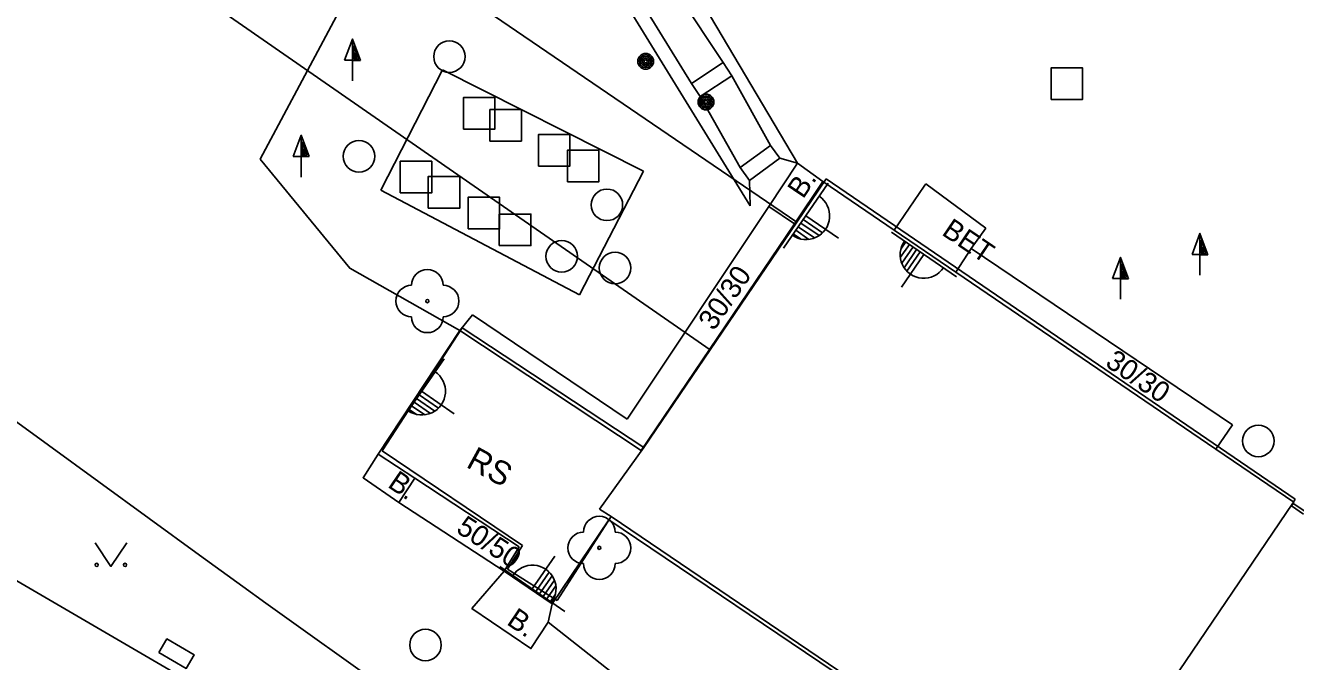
# Model space of a CAD drawing. Extents: x -540150 to -533593, y -1185082 to -1180066.
# Drawn here: x -536061.54 to -536021.28, y -1184550.12 to -1184529.96 of the extents above; entities that cross this region are included whole.
import ezdxf

# ---------------------------------------------------------------- set-up
doc = ezdxf.new("R2010")
doc.units = 0
for name, color, linetype in [('KN_HRAN_PARCEL', 7, 'Continuous'), ('KN_VKP_HRAN_', 7, 'Continuous'), ('Vrstva 10', 7, 'Continuous'), ('Vrstva 11', 7, 'Continuous'), ('Vrstva 22', 7, 'Continuous'), ('Vrstva 24', 7, 'Continuous'), ('Vrstva 25', 7, 'Continuous'), ('Vrstva 26', 7, 'Continuous'), ('Vrstva 27', 7, 'Continuous'), ('Vrstva 36', 7, 'Continuous'), ('Vrstva 37', 7, 'Continuous'), ('Vrstva 40', 7, 'Continuous'), ('Vrstva 41', 7, 'Continuous'), ('Vrstva 5', 7, 'Continuous'), ('Vrstva 7', 7, 'Continuous')]:
    doc.layers.add(name, color=color, linetype=linetype)

msp = doc.modelspace()

# ---------------------------------------------------------------- linework, layer by layer
at = {"layer": 'KN_HRAN_PARCEL'}
for p, q in [((-536036.161, -1184534.825), (-536037.091, -1184536.195)), ((-536021.291, -1184544.975), (-536036.161, -1184534.825)), ((-536037.091, -1184536.195), (-536039.841, -1184540.235)), ((-536047.701, -1184539.545), (-536050.231, -1184543.445)), ((-536041.941, -1184543.335), (-536047.701, -1184539.545)), ((-536039.841, -1184540.235), (-536041.941, -1184543.335)), ((-536050.231, -1184543.445), (-536045.781, -1184546.435)), ((-536021.371, -1184545.095), (-536021.291, -1184544.975)), ((-536019.161, -1184546.605), (-536021.371, -1184545.095)), ((-536044.691, -1184548.185), (-536042.971, -1184545.525)), ((-536042.971, -1184545.525), (-536028.361, -1184555.415)), ((-536045.781, -1184546.435), (-536046.261, -1184547.195)), ((-536046.261, -1184547.195), (-536044.691, -1184548.185))]:
    msp.add_line(p, q, dxfattribs=at)
at = {"layer": 'KN_VKP_HRAN_'}
for p, q in [((-536039.841, -1184540.235), (-536061.291, -1184525.355)), ((-536037.091, -1184536.195), (-536047.171, -1184529.325)), ((-536041.941, -1184543.335), (-536043.341, -1184545.285)), ((-536021.371, -1184545.095), (-536028.281, -1184555.295)), ((-536042.971, -1184545.525), (-536043.341, -1184545.285))]:
    msp.add_line(p, q, dxfattribs=at)
at = {"layer": 'Vrstva 10'}
for p, q in [((-536056.027, -1184546.748), (-536060.815, -1184543.257)), ((-536043.816, -1184555.48), (-536053.921, -1184548.265))]:
    msp.add_line(p, q, dxfattribs=at)
for points in [[(-536060.815, -1184543.257), (-536062.015, -1184542.388), (-536062.917, -1184541.739), (-536063.595, -1184541.254), (-536064.616, -1184540.532), (-536065.128, -1184540.173), (-536065.641, -1184539.815), (-536065.853, -1184539.669), (-536066.266, -1184539.392), (-536066.656, -1184539.138), (-536067.025, -1184538.904), (-536067.374, -1184538.689), (-536067.702, -1184538.489), (-536068.011, -1184538.304), (-536068.593, -1184537.963)], [(-536053.921, -1184548.265), (-536054.655, -1184547.739), (-536056.027, -1184546.748)]]:
    msp.add_lwpolyline(points, dxfattribs=at)
at = {"layer": 'Vrstva 11'}
for p, q in [((-536037.071, -1184534.325), (-536040.891, -1184527.865)), ((-536054.101, -1184534.195), (-536050.781, -1184527.975)), ((-536038.571, -1184535.675), (-536042.631, -1184529.075)), ((-536040.862, -1184528.963), (-536039.421, -1184531.135)), ((-536040.431, -1184531.795), (-536041.822, -1184529.543)), ((-536048.321, -1184531.365), (-536050.281, -1184535.175)), ((-536041.951, -1184534.575), (-536048.321, -1184531.365)), ((-536040.431, -1184531.795), (-536039.421, -1184531.135)), ((-536039.147, -1184531.554), (-536039.421, -1184531.135)), ((-536040.431, -1184531.795), (-536040.157, -1184532.214)), ((-536040.157, -1184532.214), (-536039.147, -1184531.554)), ((-536039.147, -1184531.554), (-536037.921, -1184533.765)), ((-536038.881, -1184534.465), (-536040.157, -1184532.214)), ((-536037.921, -1184533.765), (-536038.881, -1184534.465)), ((-536037.921, -1184533.765), (-536037.626, -1184534.169)), ((-536037.626, -1184534.169), (-536038.586, -1184534.869)), ((-536037.071, -1184534.325), (-536037.981, -1184535.695)), ((-536037.626, -1184534.169), (-536037.071, -1184534.325)), ((-536036.261, -1184534.905), (-536037.071, -1184534.325)), ((-536043.981, -1184538.495), (-536041.951, -1184534.575)), ((-536038.586, -1184534.869), (-536038.881, -1184534.465)), ((-536038.571, -1184535.675), (-536038.586, -1184534.869)), ((-536033.001, -1184534.975), (-536031.101, -1184536.385)), ((-536050.281, -1184535.175), (-536043.981, -1184538.495)), ((-536037.981, -1184535.695), (-536042.471, -1184542.435)), ((-536037.167, -1184536.245), (-536037.981, -1184535.695)), ((-536031.561, -1184537.025), (-536023.281, -1184542.615)), ((-536047.371, -1184539.125), (-536047.771, -1184539.625)), ((-536042.471, -1184542.435), (-536047.371, -1184539.125)), ((-536023.281, -1184542.615), (-536023.803, -1184543.383)), ((-536044.971, -1184548.875), (-536044.841, -1184548.285)), ((-536031.241, -1184559.645), (-536044.971, -1184548.875))]:
    msp.add_line(p, q, dxfattribs=at)
for points in [[(-536047.771, -1184539.625), (-536051.261, -1184537.655), (-536054.101, -1184534.195)], [(-536034, -1184536.443), (-536033.055, -1184535.055), (-536033.001, -1184534.975)], [(-536032.046, -1184537.773), (-536031.561, -1184537.025), (-536031.101, -1184536.385)], [(-536050.361, -1184543.545), (-536050.841, -1184544.295), (-536049.701, -1184545.075)], [(-536049.198, -1184544.31), (-536049.701, -1184545.075), (-536046.371, -1184547.255)], [(-536046.371, -1184547.255), (-536047.391, -1184548.435), (-536045.521, -1184549.705), (-536044.971, -1184548.875)]]:
    msp.add_lwpolyline(points, dxfattribs=at)
at = {"layer": 'Vrstva 22'}
for centre in [(-536048.801, -1184538.695), (-536043.351, -1184546.515)]:
    msp.add_circle(centre, 0.05, dxfattribs=at)
for centre, start, end in [((-536048.801, -1184538.195), 0, 180), ((-536049.301, -1184538.695), 90, 270), ((-536048.301, -1184538.695), 270, 90), ((-536048.801, -1184539.195), 180, 0), ((-536043.351, -1184546.015), 0, 180), ((-536043.851, -1184546.515), 90, 270), ((-536042.851, -1184546.515), 270, 90), ((-536043.351, -1184547.015), 180, 0)]:
    msp.add_arc(centre, 0.5, start, end, dxfattribs=at)
at = {"layer": 'Vrstva 24'}
msp.add_lwpolyline([(-536057.311, -1184549.832), (-536056.447, -1184550.336), (-536056.195, -1184549.904), (-536057.059, -1184549.4)], close=True, dxfattribs=at)
at = {"layer": 'Vrstva 25'}
for p, q in [((-536051.423, -1184531.063), (-536051.171, -1184530.389)), ((-536051.171, -1184531.063), (-536051.423, -1184531.063)), ((-536051.171, -1184531.715), (-536051.171, -1184531.065)), ((-536053.053, -1184534.113), (-536052.801, -1184533.439)), ((-536052.801, -1184534.113), (-536053.053, -1184534.113)), ((-536052.801, -1184534.765), (-536052.801, -1184534.115)), ((-536024.563, -1184537.223), (-536024.311, -1184536.549)), ((-536027.083, -1184537.983), (-536026.831, -1184537.309)), ((-536024.311, -1184537.223), (-536024.563, -1184537.223)), ((-536024.311, -1184537.875), (-536024.311, -1184537.225)), ((-536026.831, -1184537.983), (-536027.083, -1184537.983)), ((-536026.831, -1184538.635), (-536026.831, -1184537.985))]:
    msp.add_line(p, q, dxfattribs=at)
for points in [[(-536050.921, -1184531.065), (-536051.171, -1184531.065), (-536051.171, -1184530.389), (-536051.171, -1184530.389)], [(-536050.978, -1184531.025), (-536051.131, -1184531.025), (-536051.131, -1184530.612)], [(-536051.036, -1184530.985), (-536051.091, -1184530.985), (-536051.091, -1184530.836)], [(-536052.551, -1184534.115), (-536052.801, -1184534.115), (-536052.801, -1184533.439), (-536052.801, -1184533.439)], [(-536052.608, -1184534.075), (-536052.761, -1184534.075), (-536052.761, -1184533.662)], [(-536052.666, -1184534.035), (-536052.721, -1184534.035), (-536052.721, -1184533.886)], [(-536024.061, -1184537.225), (-536024.311, -1184537.225), (-536024.311, -1184536.549), (-536024.311, -1184536.549)], [(-536024.118, -1184537.185), (-536024.271, -1184537.185), (-536024.271, -1184536.772)], [(-536024.176, -1184537.145), (-536024.231, -1184537.145), (-536024.231, -1184536.996)], [(-536026.581, -1184537.985), (-536026.831, -1184537.985), (-536026.831, -1184537.309), (-536026.831, -1184537.309)], [(-536026.638, -1184537.945), (-536026.791, -1184537.945), (-536026.791, -1184537.532)], [(-536026.696, -1184537.905), (-536026.751, -1184537.905), (-536026.751, -1184537.756)]]:
    msp.add_lwpolyline(points, close=True, dxfattribs=at)
for centre, radius in [((-536041.881, -1184531.095), 0.25), ((-536041.881, -1184531.095), 0.2), ((-536041.881, -1184531.095), 0.15), ((-536041.881, -1184531.095), 0.1), ((-536041.881, -1184531.095), 0.05), ((-536039.971, -1184532.385), 0.25), ((-536039.971, -1184532.385), 0.2), ((-536039.971, -1184532.385), 0.15), ((-536039.971, -1184532.385), 0.1), ((-536039.971, -1184532.385), 0.05)]:
    msp.add_circle(centre, radius, dxfattribs=at)
at = {"layer": 'Vrstva 26'}
for points in [[(-536029.031, -1184532.305), (-536028.031, -1184532.305), (-536028.031, -1184531.305), (-536029.031, -1184531.305)], [(-536047.661, -1184533.245), (-536046.661, -1184533.245), (-536046.661, -1184532.245), (-536047.661, -1184532.245)], [(-536046.821, -1184533.625), (-536045.821, -1184533.625), (-536045.821, -1184532.625), (-536046.821, -1184532.625)], [(-536045.281, -1184534.415), (-536044.281, -1184534.415), (-536044.281, -1184533.415), (-536045.281, -1184533.415)], [(-536044.361, -1184534.915), (-536043.361, -1184534.915), (-536043.361, -1184533.915), (-536044.361, -1184533.915)], [(-536049.661, -1184535.265), (-536048.661, -1184535.265), (-536048.661, -1184534.265), (-536049.661, -1184534.265)], [(-536048.771, -1184535.745), (-536047.771, -1184535.745), (-536047.771, -1184534.745), (-536048.771, -1184534.745)], [(-536047.511, -1184536.405), (-536046.511, -1184536.405), (-536046.511, -1184535.405), (-536047.511, -1184535.405)], [(-536046.521, -1184536.935), (-536045.521, -1184536.935), (-536045.521, -1184535.935), (-536046.521, -1184535.935)]]:
    msp.add_lwpolyline(points, close=True, dxfattribs=at)
at = {"layer": 'Vrstva 27'}
for centre in [(-536048.101, -1184530.945), (-536050.971, -1184534.105), (-536043.111, -1184535.645), (-536044.541, -1184537.275), (-536042.851, -1184537.645), (-536022.461, -1184543.125), (-536048.861, -1184549.595)]:
    msp.add_circle(centre, 0.5, dxfattribs=at)
at = {"layer": 'Vrstva 36'}
msp.add_lwpolyline([(-536059.333, -1184546.355), (-536058.833, -1184547.105), (-536058.333, -1184546.355)], dxfattribs=at)
for centre in [(-536059.284, -1184547.055), (-536058.384, -1184547.055)]:
    msp.add_circle(centre, 0.05, dxfattribs=at)
at = {"layer": 'Vrstva 37'}
for p, q in [((-536036.097, -1184534.96), (-536037.515, -1184537.02)), ((-536037.044, -1184536.336), (-536036.525, -1184536.693)), ((-536036.965, -1184536.221), (-536036.385, -1184536.62)), ((-536036.885, -1184536.105), (-536036.272, -1184536.528)), ((-536036.806, -1184535.99), (-536035.77, -1184536.703)), ((-536037.203, -1184536.567), (-536036.974, -1184536.724)), ((-536037.123, -1184536.451), (-536036.706, -1184536.739)), ((-536032.031, -1184537.924), (-536034.091, -1184536.506)), ((-536033.522, -1184536.898), (-536033.81, -1184537.315)), ((-536033.638, -1184536.818), (-536033.795, -1184537.047)), ((-536033.407, -1184536.977), (-536033.764, -1184537.496)), ((-536033.292, -1184537.056), (-536033.691, -1184537.636)), ((-536033.176, -1184537.136), (-536033.599, -1184537.749)), ((-536033.061, -1184537.215), (-536033.774, -1184538.251)), ((-536048.274, -1184540.52), (-536049.692, -1184542.58)), ((-536048.983, -1184541.55), (-536047.947, -1184542.263)), ((-536049.221, -1184541.896), (-536048.702, -1184542.253)), ((-536049.142, -1184541.781), (-536048.562, -1184542.18)), ((-536049.062, -1184541.665), (-536048.449, -1184542.088)), ((-536049.38, -1184542.127), (-536049.151, -1184542.284)), ((-536049.3, -1184542.011), (-536048.883, -1184542.299)), ((-536045.477, -1184547.818), (-536044.764, -1184546.782)), ((-536046.507, -1184547.109), (-536044.447, -1184548.527)), ((-536045.362, -1184547.897), (-536044.939, -1184547.284)), ((-536045.246, -1184547.977), (-536044.847, -1184547.397)), ((-536045.131, -1184548.056), (-536044.774, -1184547.537)), ((-536045.016, -1184548.135), (-536044.728, -1184547.718)), ((-536044.9, -1184548.215), (-536044.743, -1184547.986))]:
    msp.add_line(p, q, dxfattribs=at)
for centre, start, end in [((-536036.8, -1184535.995), 234.8473, 56.0933), ((-536033.066, -1184537.222), 144.8473, 326.0933), ((-536048.977, -1184541.555), 234.8473, 56.0933), ((-536045.473, -1184547.812), 324.8473, 146.0933)]:
    msp.add_arc(centre, 0.75, start, end, dxfattribs=at)
at = {"layer": 'Vrstva 5'}
for p, q in [((-536036.261, -1184534.905), (-536037.167, -1184536.245)), ((-536034, -1184536.443), (-536036.261, -1184534.905)), ((-536037.167, -1184536.245), (-536042.021, -1184543.425)), ((-536032.046, -1184537.773), (-536034, -1184536.443)), ((-536023.803, -1184543.383), (-536032.046, -1184537.773)), ((-536047.771, -1184539.625), (-536050.361, -1184543.545)), ((-536042.021, -1184543.425), (-536047.771, -1184539.625)), ((-536050.361, -1184543.545), (-536049.198, -1184544.31)), ((-536021.331, -1184545.065), (-536023.803, -1184543.383)), ((-536049.198, -1184544.31), (-536045.891, -1184546.485)), ((-536021.412, -1184545.184), (-536021.331, -1184545.065)), ((-536021.031, -1184545.445), (-536021.412, -1184545.184)), ((-536043.054, -1184545.63), (-536044.841, -1184548.285)), ((-536033.874, -1184551.809), (-536043.054, -1184545.63)), ((-536045.891, -1184546.485), (-536046.371, -1184547.255)), ((-536046.371, -1184547.255), (-536044.841, -1184548.285))]:
    msp.add_line(p, q, dxfattribs=at)
at = {"layer": 'Vrstva 7'}
msp.add_line((-536053.461, -1184552.425), (-536074.121, -1184540.395), dxfattribs=at)

# ---------------------------------------------------------------- texts
at = {"layer": 'Vrstva 40'}
for s, rotation, p in [('B.', 55.9391, (-536036.892, -1184535.481)), ('BET', 325.7644, (-536032.528, -1184536.574)), ('30/30', 55.9391, (-536039.719, -1184539.663)), ('30/30', 325.7644, (-536027.348, -1184540.729)), ('B.', 325.6197, (-536050.092, -1184544.566)), ('50/50', 326.789, (-536047.925, -1184545.999)), ('B.', 325.8178, (-536046.32, -1184548.92))]:
    msp.add_text(s, height=0.65, rotation=rotation, dxfattribs=at).set_placement(p)
at = {"layer": 'Vrstva 41'}
msp.add_text('RS', height=0.75, rotation=331.2139, dxfattribs=at).set_placement((-536047.606, -1184543.936))

doc.saveas('drawing.dxf')
